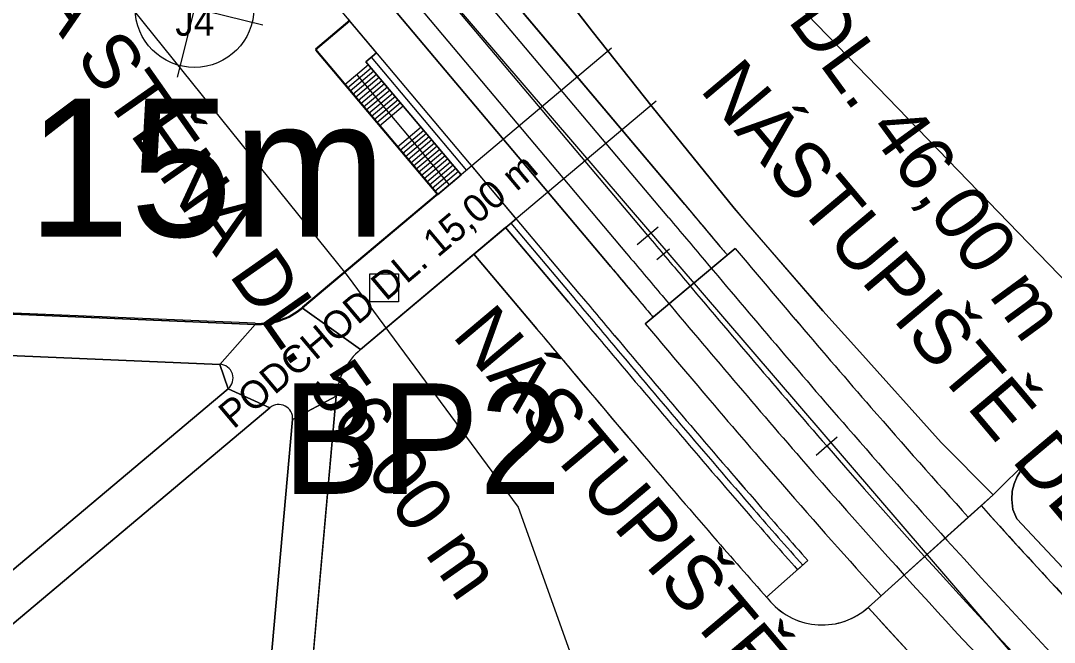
# Model space of a CAD drawing. Extents: x -606444 to -604546, y -1158114 to -1156869.
# Drawn here: x -605089.5 to -605014.7, y -1157453.4 to -1157408.3 of the extents above; entities that cross this region are included whole.
import ezdxf

# ---------------------------------------------------------------- set-up
doc = ezdxf.new("R2010")
doc.units = 0
for name, color, linetype in [('B_CHOD', 7, 'Continuous'), ('B_TRAM', 7, 'Continuous'), ('B_ZELEN', 7, 'Continuous'), ('geofyzikální profily_předběžný GTP', 7, 'Continuous'), ('jádrové vrty_předběžný GTP', 7, 'Continuous'), ('korozní průzkum', 7, 'Continuous'), ('NS_VB', 7, 'Continuous'), ('NS_VB_OBJ', 7, 'Continuous'), ('NS_VB_POP', 7, 'Continuous'), ('NS_VB_SVAHY', 7, 'Continuous'), ('OSA', 7, 'Continuous'), ('OSAPOP', 7, 'Continuous'), ('podélný profil trasou tramvaje', 7, 'Continuous'), ('sondy současného průzkumu', 7, 'Continuous')]:
    doc.layers.add(name, color=color, linetype=linetype)

# ---------------------------------------------------------------- blocks, each defined once
blk = doc.blocks.new('IG vrt podr')
at = {"layer": 'sondy současného průzkumu'}
for p, q in [((0.412, 1.649), (-0.418, -1.672)), ((-1.698, 0.422), (1.644, -0.408))]:
    blk.add_line(p, q, dxfattribs=at)
blk.add_circle((-0.002, 0.001), 1.434, dxfattribs=at)

msp = doc.modelspace()

# ---------------------------------------------------------------- linework, layer by layer
at = {"layer": 'B_CHOD'}
for p, q in [((-605065.706, -1157408.383), (-605068.193, -1157410.475)), ((-605063.775, -1157410.679), (-605065.706, -1157408.383)), ((-605068.193, -1157410.475), (-605059.375, -1157420.96)), ((-605064.54, -1157411.323), (-605063.775, -1157410.679)), ((-605057.653, -1157419.512), (-605064.54, -1157411.323)), ((-605059.375, -1157420.96), (-605057.653, -1157419.512))]:
    msp.add_line(p, q, dxfattribs=at)
for points in [[(-605063.634, -1157395.311), (-605041.47, -1157421.663), (-605038.896, -1157424.722)], [(-605020.942, -1157444.312), (-605019.149, -1157442.695), (-605022.9, -1157438.91), (-605029, -1157432.1), (-605031.48, -1157429.37), (-605037.89, -1157421.92), (-605043.83, -1157414.58), (-605048.16, -1157409.11), (-605053.06, -1157402.78), (-605053.68, -1157401.97), (-605053.4, -1157401.77), (-605057.995, -1157396.306), (-605057.642, -1157395.638)], [(-605046.828, -1157426.168), (-605068.989, -1157399.819)], [(-605071.29, -1157401.745), (-605049.124, -1157428.099)], [(-605056.888, -1157418.868), (-605069.141, -1157429.174), (-605064.93, -1157432.166), (-605053.669, -1157422.695), (-605056.888, -1157418.868)], [(-605049.889, -1157428.743), (-605054.435, -1157423.338), (-605056.731, -1157425.269), (-605052.185, -1157430.674)], [(-605038.392, -1157425.321), (-605037.818, -1157424.838)], [(-605127.071, -1157431.03), (-605075.118, -1157433.238), (-605072.572, -1157430.343), (-605128.42, -1157427.97), (-605127.071, -1157431.03)], [(-605064.93, -1157432.166), (-605069.141, -1157429.174)], [(-605044.319, -1157430.314), (-605043.746, -1157429.831)], [(-605072.572, -1157430.343), (-605075.118, -1157433.238)], [(-605074.517, -1157435.002), (-605105.209, -1157460.816), (-605102.311, -1157462.298), (-605071.494, -1157436.38), (-605074.517, -1157435.002)], [(-605074.517, -1157435.002), (-605071.494, -1157436.38)], [(-605068.879, -1157460.096), (-605066.692, -1157435.548), (-605069.854, -1157437.234), (-605071.853, -1157459.665)], [(-605069.854, -1157437.234), (-605066.692, -1157435.548)], [(-605032.549, -1157447.456), (-605033.298, -1157448.119)], [(-605028.167, -1157450.827), (-605027.254, -1157450.004)]]:
    msp.add_lwpolyline(points, dxfattribs=at)
for centre, radius, start, end in [((-603893.841, -1156461.221), 1496.491, 220.078765, 220.108735), ((-603633.011, -1156240.44), 1837.466, 220.134365, 220.358736), ((-599958.751, -1153147.584), 6647.917, 220.0606162, 220.1018719), ((-601571.087, -1154504.137), 4544.819, 220.053549, 220.104018), ((-600451.897, -1153562.399), 6006.508, 220.0596923, 220.0978757), ((-605072.36, -1157425.348), 5, 267.5668, 310.06606), ((-603665.521, -1156267.538), 1809.896, 219.989983, 220.371731), ((-603635.602, -1156242.633), 1842.572, 220.13404, 220.359061), ((-604508.881, -1156984.776), 688.038, 220.358736, 221.021076), ((-603730.016, -1156322.624), 1721.077, 220.097876, 220.365319), ((-605061.712, -1157435.992), 5, 130.06606, 174.90788), ((-603666.667, -1156269.03), 1805.056, 220.104018, 220.359183), ((-605075.161, -1157434.237), 1, 310.06606, 87.5668), ((-605070.85, -1157437.145), 1, 354.90788, 130.06606), ((-604508.852, -1156984.752), 696.576, 220.359061, 221.020895), ((-604578.509, -1157045.348), 595.75, 221.021076, 222.042549), ((-604498.769, -1156976.082), 712.124, 220.365319, 221.014674), ((-604508.841, -1156984.742), 699.84, 220.359183, 221.020827), ((-604488.007, -1156966.829), 730.316, 220.371731, 221.008328), ((-604578.509, -1157045.349), 604.25, 221.020895, 222.042549), ((-604589.327, -1157054.844), 592.106, 221.014674, 221.534935), ((-604578.509, -1157045.349), 607.5, 221.020827, 221.528761), ((-604598.403, -1157062.822), 584.022, 221.008328, 221.581853), ((-605031.516, -1157447.113), 5.001, 221.58185, 312.03011)]:
    msp.add_arc(centre, radius, start, end, dxfattribs=at)
at = {"layer": 'B_TRAM'}
for p, q in [((-605041.47, -1157421.663), (-605063.634, -1157395.311)), ((-605068.989, -1157399.819), (-605046.828, -1157426.168)), ((-605037.818, -1157424.838), (-605044.319, -1157430.314)), ((-605043.746, -1157429.831), (-605038.392, -1157425.321)), ((-605020.013, -1157443.475), (-605028.183, -1157450.841)), ((-605027.254, -1157450.004), (-605020.942, -1157444.312))]:
    msp.add_line(p, q, dxfattribs=at)
for centre, radius, start, end in [((-600451.898, -1153562.4), 5996.507, 220.059687, 220.0978916), ((-603893.84, -1156461.221), 1496.492, 220.078765, 220.108735), ((-603893.84, -1156461.221), 1495.742, 220.108735, 220.384366), ((-600451.896, -1153562.399), 6003.508, 220.0596907, 220.0978804), ((-603893.84, -1156461.221), 1503.492, 220.078809, 220.108735), ((-603893.84, -1156461.221), 1504.242, 220.108735, 220.384366), ((-604465.117, -1156947.147), 745.754, 220.384366, 220.995445), ((-604465.117, -1156947.147), 754.254, 220.384366, 220.995589), ((-604578.509, -1157045.348), 595.75, 221.021076, 222.042549), ((-604578.509, -1157045.349), 604.25, 221.020895, 222.042549), ((-604578.509, -1157045.348), 594.5, 222.042549, 233.601582), ((-604578.509, -1157045.348), 605.5, 222.042549, 233.601582)]:
    msp.add_arc(centre, radius, start, end, dxfattribs=at)
at = {"layer": 'B_ZELEN'}
for p, q in [((-605065.705, -1157408.309), (-605068.192, -1157410.401)), ((-605068.192, -1157410.401), (-605059.374, -1157420.885)), ((-605059.374, -1157420.885), (-605069.14, -1157429.1)), ((-605056.731, -1157425.269), (-605064.93, -1157432.166)), ((-605052.185, -1157430.674), (-605056.731, -1157425.269)), ((-605072.571, -1157430.268), (-605128.419, -1157427.895)), ((-605066.692, -1157435.548), (-605068.879, -1157460.096)), ((-605071.494, -1157436.38), (-605102.311, -1157462.298)), ((-605071.853, -1157459.665), (-605069.854, -1157437.234))]:
    msp.add_line(p, q, dxfattribs=at)
for points in [[(-605112.2, -1157451.29), (-605106.78, -1157457.79), (-605105.209, -1157460.816), (-605074.517, -1157435.002), (-605075.118, -1157433.238), (-605127.071, -1157431.03), (-605127.04, -1157431.1), (-605124.61, -1157437.06), (-605123.94, -1157436.79), (-605121.79, -1157435.88), (-605120.08, -1157439.98), (-605118.85, -1157439.46), (-605117.89, -1157441.73), (-605119.1, -1157442.21), (-605117, -1157447.24), (-605115.76, -1157446.7), (-605114.03, -1157450.62), (-605113.264, -1157451.918), (-605112.2, -1157451.29)], [(-605075.118, -1157433.238), (-605074.517, -1157435.002)], [(-605003.88, -1157449.12), (-605003.59, -1157448.97), (-605003.24, -1157448.95), (-605002.92, -1157449.08), (-605002.67, -1157449.29), (-605005.49, -1157446.33), (-605010.36, -1157450.85), (-605010.84, -1157450.88), (-605011.22, -1157450.78), (-605011.6, -1157450.58), (-605011.93, -1157450.29), (-605017.42, -1157444.44), (-605017.72, -1157443.76), (-605017.79, -1157443.02), (-605017.76, -1157442.43), (-605017.62, -1157441.89), (-605017.39, -1157441.35), (-605017.01, -1157440.74), (-605016.51, -1157440.08), (-605019.149, -1157442.695), (-605020.013, -1157443.475)], [(-605028.183, -1157450.841), (-605028.183, -1157450.841)]]:
    msp.add_lwpolyline(points, dxfattribs=at)
for centre, radius, start, end in [((-605072.359, -1157425.273), 5, 267.5668, 310.06606), ((-600451.895, -1153562.397), 6010.51, 220.0596944, 220.0978693), ((-605061.712, -1157435.992), 5, 130.06606, 174.90788), ((-605075.161, -1157434.237), 1, 310.06606, 87.5668), ((-603893.84, -1156461.221), 1510.492, 220.078854, 220.384366), ((-605070.85, -1157437.145), 1, 354.90788, 130.06606), ((-604465.117, -1156947.147), 760.504, 220.384366, 220.995693), ((-604578.509, -1157045.348), 594.5, 222.042549, 223.599351), ((-604578.509, -1157045.349), 610.5, 221.020765, 221.569416), ((-605031.516, -1157447.114), 5, 221.56942, 311.80598), ((-604578.509, -1157045.348), 605.5, 222.042549, 224.551067)]:
    msp.add_arc(centre, radius, start, end, dxfattribs=at)
at = {"layer": 'geofyzikální profily_předběžný GTP'}
for points in [[(-605670.777, -1157141.05), (-605656.017, -1157139.471), (-605613.877, -1157139.359), (-605584.802, -1157137.32), (-605531.406, -1157136.329), (-605491.561, -1157133.405), (-605482.073, -1157135.613), (-605438.781, -1157126.664), (-605383.232, -1157124.522), (-605352.341, -1157123.33), (-605321.946, -1157125.999), (-605284.139, -1157130.42), (-605243.303, -1157142.595), (-605207.83, -1157158.833), (-605179.979, -1157186.151), (-605165.292, -1157202.666), (-605149.231, -1157223.341), (-605135.067, -1157244.471), (-605115.915, -1157286.275), (-605103.218, -1157315.843), (-605095.331, -1157330.321), (-605036.966, -1157403.361), (-604999.079, -1157442.536), (-604970.798, -1157468.352)], [(-605668.887, -1157175.563), (-605638.047, -1157172.713), (-605616.091, -1157172.842), (-605512.92, -1157173.16), (-605468.488, -1157175.648), (-605413.499, -1157174.062), (-605313.444, -1157169.44), (-605274.571, -1157178.007), (-605221.389, -1157204.274), (-605178.573, -1157224.003), (-605160.32, -1157243.281), (-605143.644, -1157289.502), (-605117.165, -1157349.927), (-605096.208, -1157389.159), (-605065.898, -1157426.812), (-605053.52, -1157443.58), (-605045.82, -1157465.15), (-605020.205, -1157502.195)]]:
    msp.add_lwpolyline(points, dxfattribs=at)
at = {"layer": 'korozní průzkum'}
msp.add_lwpolyline([(-605064.26, -1157426.685), (-605062.179, -1157426.685), (-605062.179, -1157428.721), (-605064.26, -1157428.721)], close=True, dxfattribs=at)
at = {"layer": 'NS_VB'}
for p, q in [((-605053.06, -1157402.78), (-605048.16, -1157409.11)), ((-605065.706, -1157408.383), (-605068.193, -1157410.475)), ((-605048.16, -1157409.11), (-605043.83, -1157414.58)), ((-605063.775, -1157410.679), (-605064.54, -1157411.323)), ((-605043.83, -1157414.58), (-605037.89, -1157421.92)), ((-605056.888, -1157418.868), (-605069.141, -1157429.174)), ((-605037.89, -1157421.92), (-605036.9, -1157423.11)), ((-605053.669, -1157422.695), (-605064.93, -1157432.166)), ((-605036.9, -1157423.11), (-605031.48, -1157429.37)), ((-605038.392, -1157425.321), (-605037.818, -1157424.838)), ((-605128.42, -1157427.97), (-605072.572, -1157430.343)), ((-605031.48, -1157429.37), (-605029, -1157432.1)), ((-605044.319, -1157430.314), (-605043.746, -1157429.831)), ((-605127.071, -1157431.03), (-605075.118, -1157433.238)), ((-605029, -1157432.1), (-605022.9, -1157438.91)), ((-605074.517, -1157435.002), (-605105.209, -1157460.816)), ((-605066.692, -1157435.548), (-605068.879, -1157460.096)), ((-605071.494, -1157436.38), (-605102.311, -1157462.298)), ((-605069.854, -1157437.234), (-605071.853, -1157459.665)), ((-605022.9, -1157438.91), (-605019.149, -1157442.695)), ((-605016.51, -1157440.08), (-605019.149, -1157442.695)), ((-605016.51, -1157440.08), (-605017.01, -1157440.74)), ((-605017.39, -1157441.35), (-605017.62, -1157441.89)), ((-605017.01, -1157440.74), (-605017.39, -1157441.35)), ((-605017.62, -1157441.89), (-605017.76, -1157442.43)), ((-605019.149, -1157442.695), (-605020.942, -1157444.312)), ((-605017.76, -1157442.43), (-605017.79, -1157443.02)), ((-605017.79, -1157443.02), (-605017.72, -1157443.76)), ((-605017.72, -1157443.76), (-605017.42, -1157444.44)), ((-605011.93, -1157450.29), (-605017.42, -1157444.44)), ((-605032.549, -1157447.456), (-605035.544, -1157450.107)), ((-605027.254, -1157450.004), (-605028.167, -1157450.827))]:
    msp.add_line(p, q, dxfattribs=at)
for points in [[(-605041.47, -1157421.663), (-605063.634, -1157395.311)], [(-605068.989, -1157399.819), (-605046.828, -1157426.168)], [(-605071.285, -1157401.751), (-605049.124, -1157428.099)], [(-605068.193, -1157410.475), (-605059.375, -1157420.96)], [(-605064.54, -1157411.323), (-605057.653, -1157419.512)], [(-605054.435, -1157423.338), (-605049.889, -1157428.743)], [(-605056.731, -1157425.269), (-605052.185, -1157430.674)]]:
    msp.add_lwpolyline(points, dxfattribs=at)
for centre, radius, start, end in [((-600451.898, -1153562.4), 5996.507, 220.059687, 220.0978916), ((-603893.84, -1156461.221), 1496.492, 220.078765, 220.108735), ((-603893.84, -1156461.221), 1495.742, 220.108735, 220.384366), ((-600451.896, -1153562.399), 6003.508, 220.0596907, 220.0978804), ((-600451.895, -1153562.398), 6007.51, 220.0596929, 220.0978741), ((-600451.896, -1153562.398), 6006.509, 220.0596923, 220.0978757), ((-605072.36, -1157425.348), 5, 267.5668, 310.06606), ((-603893.84, -1156461.221), 1503.492, 220.078809, 220.108735), ((-600451.895, -1153562.397), 6010.51, 220.0596944, 220.0978693), ((-603893.84, -1156461.221), 1504.242, 220.108735, 220.384366), ((-604465.117, -1156947.147), 745.754, 220.384366, 220.995445), ((-603893.84, -1156461.221), 1506.492, 220.078828, 220.384366), ((-605061.712, -1157435.992), 5, 130.06606, 174.90788), ((-603893.84, -1156461.221), 1507.492, 220.078835, 220.384366), ((-605075.161, -1157434.237), 1, 310.06606, 87.5668), ((-603893.84, -1156461.221), 1510.492, 220.078854, 220.384366), ((-605070.85, -1157437.145), 1, 354.90788, 130.06606), ((-604465.117, -1156947.147), 754.254, 220.384366, 220.995589), ((-604578.509, -1157045.348), 595.75, 221.021076, 222.042549), ((-604465.117, -1156947.147), 756.504, 220.384366, 220.995627), ((-604465.117, -1156947.147), 757.504, 220.384366, 220.995644), ((-604465.117, -1156947.147), 760.504, 220.384366, 220.995693), ((-604578.509, -1157045.349), 604.25, 221.020895, 222.042549), ((-604578.509, -1157045.349), 606.5, 221.020848, 221.528761), ((-604578.509, -1157045.348), 594.5, 222.042549, 233.601555), ((-604578.509, -1157045.349), 607.5, 221.020827, 221.528761), ((-604578.509, -1157045.349), 610.5, 221.020765, 221.569416), ((-605031.516, -1157447.114), 5, 221.56942, 312.04255), ((-604578.509, -1157045.348), 605.5, 222.042549, 233.601556)]:
    msp.add_arc(centre, radius, start, end, dxfattribs=at)
at = {"layer": 'NS_VB_OBJ'}
for p, q in [((-605046.76, -1157410.35), (-605056.888, -1157418.868)), ((-605043.542, -1157414.177), (-605053.669, -1157422.695))]:
    msp.add_line(p, q, dxfattribs=at)
for points in [[(-605064.158, -1157411.001), (-605057.27, -1157419.19)], [(-605054.052, -1157423.016), (-605049.506, -1157428.421)]]:
    msp.add_lwpolyline(points, dxfattribs=at)
for centre, radius, start, end in [((-600451.895, -1153562.397), 6007.01, 220.0596926, 220.0978749), ((-603893.84, -1156461.221), 1506.992, 220.078831, 220.384366), ((-604465.117, -1156947.147), 757.004, 220.384366, 220.995635), ((-604578.509, -1157045.349), 607, 221.020838, 221.528761)]:
    msp.add_arc(centre, radius, start, end, dxfattribs=at)
at = {"layer": 'NS_VB_SVAHY'}
for p, q in [((-605064.347, -1157411.553), (-605066.069, -1157413.001)), ((-605064.154, -1157411.782), (-605065.876, -1157413.23)), ((-605063.961, -1157412.012), (-605065.683, -1157413.46)), ((-605063.768, -1157412.241), (-605065.49, -1157413.69)), ((-605065.208, -1157412.277), (-605058.514, -1157420.236)), ((-605063.575, -1157412.471), (-605065.297, -1157413.919)), ((-605063.382, -1157412.701), (-605065.104, -1157414.149)), ((-605063.189, -1157412.93), (-605064.91, -1157414.378)), ((-605062.995, -1157413.16), (-605064.717, -1157414.608)), ((-605062.802, -1157413.389), (-605064.524, -1157414.838)), ((-605062.609, -1157413.619), (-605064.331, -1157415.067)), ((-605062.416, -1157413.848), (-605064.138, -1157415.297)), ((-605062.223, -1157414.078), (-605063.945, -1157415.526)), ((-605062.03, -1157414.308), (-605063.752, -1157415.756)), ((-605061.837, -1157414.537), (-605063.559, -1157415.985)), ((-605060.549, -1157416.068), (-605062.271, -1157417.516)), ((-605060.356, -1157416.297), (-605062.078, -1157417.746)), ((-605060.163, -1157416.527), (-605061.885, -1157417.975)), ((-605059.97, -1157416.757), (-605061.692, -1157418.205)), ((-605059.777, -1157416.986), (-605061.499, -1157418.434)), ((-605059.584, -1157417.216), (-605061.306, -1157418.664)), ((-605059.391, -1157417.445), (-605061.113, -1157418.894)), ((-605059.198, -1157417.675), (-605060.92, -1157419.123)), ((-605059.005, -1157417.905), (-605060.727, -1157419.353)), ((-605058.812, -1157418.134), (-605060.534, -1157419.582)), ((-605058.618, -1157418.364), (-605060.34, -1157419.812)), ((-605058.425, -1157418.593), (-605060.147, -1157420.042)), ((-605058.232, -1157418.823), (-605059.954, -1157420.271)), ((-605058.039, -1157419.053), (-605059.761, -1157420.501)), ((-605057.846, -1157419.282), (-605059.568, -1157420.73))]:
    msp.add_line(p, q, dxfattribs=at)
at = {"layer": 'OSA'}
msp.add_line((-605044.149, -1157423.916), (-605066.312, -1157397.565), dxfattribs=at)
for points in [[(-605042.618, -1157422.628), (-605064.782, -1157396.277)], [(-605067.842, -1157398.853), (-605045.68, -1157425.203)]]:
    msp.add_lwpolyline(points, dxfattribs=at)
for centre, radius, start, end in [((-600451.896, -1153562.399), 5998.008, 220.0596878, 220.0978892), ((-600451.897, -1153562.4), 6000.007, 220.0596889, 220.097886), ((-600451.896, -1153562.398), 6002.008, 220.0596899, 220.0978828), ((-603893.84, -1156461.221), 1497.992, 220.078774, 220.384366), ((-603893.84, -1156461.221), 1499.992, 220.078787, 220.384366), ((-603893.84, -1156461.221), 1501.992, 220.0788, 220.384366), ((-604465.117, -1156947.147), 748.004, 220.384366, 220.995484), ((-604465.117, -1156947.147), 750.004, 220.384366, 220.995518), ((-604465.117, -1156947.147), 752.004, 220.384366, 220.995552), ((-604578.509, -1157045.348), 598, 221.021027, 222.061049), ((-604578.509, -1157045.349), 600, 221.020985, 233.601556), ((-604578.509, -1157045.348), 602, 221.020942, 226.476915), ((-604591.873, -1157057.407), 580, 222.061049, 233.726434)]:
    msp.add_arc(centre, radius, start, end, dxfattribs=at)
at = {"layer": 'OSAPOP'}
for p, q in [((-605044.914, -1157424.559), (-605043.384, -1157423.272)), ((-605043.486, -1157425.636), (-605042.567, -1157424.864)), ((-605031.945, -1157439.806), (-605030.436, -1157438.493))]:
    msp.add_line(p, q, dxfattribs=at)
at = {"layer": 'podélný profil trasou tramvaje'}
msp.add_lwpolyline([(-604973.887, -1157496.654), (-605009.522, -1157463.782), (-605083.895, -1157377.089), (-605085.67, -1157373.96), (-605102.483, -1157348.991)], dxfattribs=at)

# ---------------------------------------------------------------- block references
at = {"layer": 'jádrové vrty_předběžný GTP', "xscale": 3, "yscale": 3}
msp.add_blockref('IG vrt podr', (-605076.95, -1157407.434), dxfattribs=at)

# ---------------------------------------------------------------- texts
msp.add_text('J4', height=2).set_placement((-605078.343, -1157409.435))
at = {"layer": 'jádrové vrty_předběžný GTP'}
msp.add_text('J4, 15m', height=10, dxfattribs=at).set_placement((-605110.616, -1157423.985))
at = {"layer": 'korozní průzkum'}
msp.add_text('BP2', height=8, dxfattribs=at).set_placement((-605070.609, -1157442.622))
at = {"layer": 'NS_VB_POP'}
for s, rotation, p in [('NÍZKÁ PROTIHLUKOVÁ STĚNA DL. 46,00 m', 306.15054, (-605081.229, -1157343.767)), ('NÍZKÁ PROTIHLUKOVÁ STĚNA DL. 56,00 m', 305.08639, (-605120.474, -1157361.331)), ('NÁSTUPIŠTĚ DL. 44,00 m', 310.06606, (-605040.444, -1157413.36)), ('NÁSTUPIŠTĚ DL. 44,00 m', 310.06606, (-605058.375, -1157431.172))]:
    msp.add_text(s, height=4, rotation=rotation, dxfattribs=at).set_placement(p)
at = {"layer": 'OSAPOP'}
msp.add_text('PODCHOD DL. 15,00 m', height=2, rotation=40.06606, dxfattribs=at).set_placement((-605074.125, -1157437.982))

doc.saveas('drawing.dxf')
